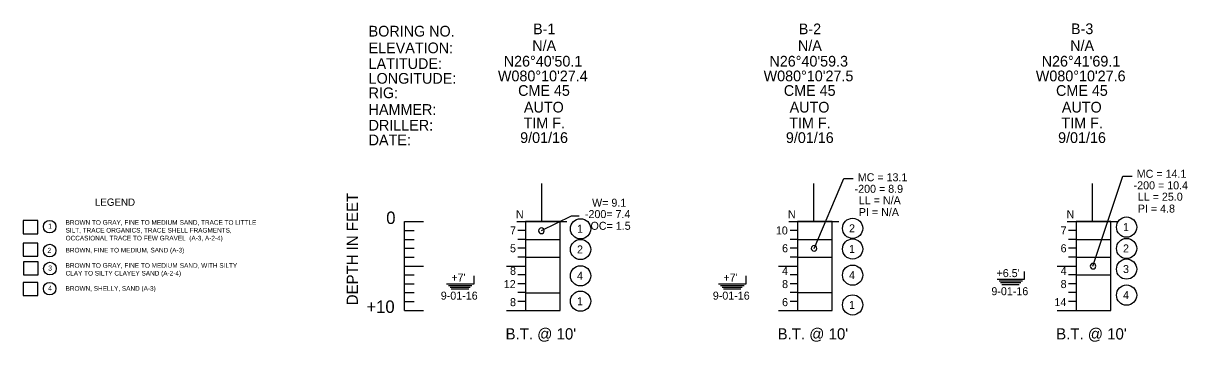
# Model space of a CAD drawing. Extents: x 0 to 331, y -72 to 117.
# Drawn here: x 9.92 to 45.01, y 22.82 to 32.42 of the extents above; entities that cross this region are included whole.
import ezdxf

# ---------------------------------------------------------------- set-up
doc = ezdxf.new("R2010")
doc.units = 0
for name, color, linetype in [('1-BORE', 7, 'Continuous'), ('1-GRID', 7, 'Continuous'), ('1-TEXT', 7, 'Continuous')]:
    doc.layers.add(name, color=color, linetype=linetype)

msp = doc.modelspace()

# ---------------------------------------------------------------- linework, layer by layer
at = {"layer": '1-BORE'}
for p, q in [((33.75, 25.629), (34.653, 27.737)), ((34.653, 27.737), (34.93, 27.738)), ((42.158, 25.092), (43.062, 27.802)), ((43.062, 27.802), (43.338, 27.803)), ((25.535, 26.168), (26.439, 26.607)), ((26.439, 26.607), (26.667, 26.607)), ((25.056, 25.902), (26.101, 25.902)), ((33.255, 25.902), (34.3, 25.902)), ((41.65, 25.902), (42.695, 25.902)), ((25.056, 25.366), (26.101, 25.366)), ((33.255, 25.366), (34.3, 25.366)), ((41.65, 25.366), (42.695, 25.366)), ((41.65, 24.83), (42.695, 24.83)), ((25.056, 24.294), (26.101, 24.294)), ((33.255, 24.295), (34.3, 24.295)), ((25.056, 23.759), (26.101, 23.759)), ((33.255, 23.759), (34.3, 23.759)), ((41.65, 23.759), (42.695, 23.759))]:
    msp.add_line(p, q, dxfattribs=at)
for points in [[(26.101, 23.759), (26.101, 26.438), (25.056, 26.438), (25.056, 23.759)], [(34.3, 23.759), (34.3, 26.438), (33.255, 26.438), (33.255, 23.759)], [(42.695, 23.759), (42.695, 26.438), (41.65, 26.438), (41.65, 23.759)]]:
    msp.add_lwpolyline(points, dxfattribs=at)
for centre, start, end in [((25.533, 26.161), 0, 180), ((25.533, 26.161), 180, 0), ((33.75, 25.631), 0, 180), ((33.75, 25.631), 180, 0), ((42.159, 25.094), 0, 180), ((42.159, 25.094), 180, 0)]:
    msp.add_arc(centre, 0.0848, start, end, dxfattribs=at)
at = {"layer": '1-GRID'}
for p, q in [((21.411, 26.438), (21.976, 26.438)), ((21.411, 26.17), (21.697, 26.17)), ((21.411, 25.902), (21.697, 25.902)), ((21.411, 25.634), (21.697, 25.634)), ((21.411, 25.366), (21.697, 25.366)), ((21.411, 25.098), (21.976, 25.098)), ((21.411, 25.098), (21.976, 25.098)), ((21.411, 24.83), (21.697, 24.83)), ((21.411, 24.563), (21.697, 24.563)), ((21.411, 24.295), (21.697, 24.295)), ((21.411, 24.027), (21.697, 24.027)), ((21.411, 23.759), (21.976, 23.759))]:
    msp.add_line(p, q, dxfattribs=at)
msp.add_lwpolyline([(21.411, 23.759), (21.411, 26.438)], dxfattribs=at)
at = {"layer": '1-TEXT'}
for p, q in [((25.535, 27.589), (25.535, 26.438)), ((33.735, 27.589), (33.735, 26.438)), ((42.13, 27.589), (42.13, 26.438)), ((25.056, 26.17), (24.826, 26.17)), ((33.255, 26.17), (33.026, 26.17)), ((41.65, 26.17), (41.421, 26.17)), ((25.056, 25.902), (24.826, 25.902)), ((25.056, 25.634), (24.826, 25.634)), ((33.255, 25.902), (33.026, 25.902)), ((33.255, 25.634), (33.026, 25.634)), ((41.65, 25.902), (41.421, 25.902)), ((41.65, 25.634), (41.421, 25.634)), ((25.056, 25.366), (24.826, 25.366)), ((33.255, 25.366), (33.026, 25.366)), ((41.65, 25.366), (41.421, 25.366)), ((24.482, 25.098), (25.056, 25.098)), ((32.682, 25.098), (33.255, 25.098)), ((40.097, 24.697), (40.097, 24.932)), ((41.077, 25.098), (41.65, 25.098)), ((23.502, 24.563), (23.502, 24.798)), ((25.056, 24.83), (24.826, 24.83)), ((31.702, 24.563), (31.702, 24.798)), ((33.255, 24.83), (33.026, 24.83)), ((39.272, 24.697), (40.097, 24.697)), ((39.326, 24.648), (40.036, 24.648)), ((39.374, 24.599), (39.98, 24.599)), ((41.65, 24.83), (41.421, 24.83)), ((22.677, 24.563), (23.502, 24.563)), ((22.731, 24.514), (23.441, 24.514)), ((22.779, 24.465), (23.385, 24.465)), ((22.817, 24.406), (23.342, 24.406)), ((25.056, 24.563), (24.826, 24.563)), ((25.056, 24.295), (24.826, 24.295)), ((30.876, 24.563), (31.702, 24.563)), ((30.931, 24.514), (31.641, 24.514)), ((30.978, 24.465), (31.585, 24.465)), ((31.017, 24.406), (31.541, 24.406)), ((33.255, 24.563), (33.026, 24.563)), ((33.255, 24.295), (33.026, 24.295)), ((39.412, 24.54), (39.937, 24.54)), ((41.65, 24.563), (41.421, 24.563)), ((41.65, 24.295), (41.421, 24.295)), ((25.056, 24.027), (24.826, 24.027)), ((33.255, 24.027), (33.026, 24.027)), ((41.65, 24.027), (41.421, 24.027)), ((24.482, 23.759), (25.056, 23.759)), ((32.682, 23.759), (33.255, 23.759)), ((41.077, 23.759), (41.65, 23.759))]:
    msp.add_line(p, q, dxfattribs=at)
for points in [[(9.918, 26.073), (10.36, 26.073), (10.36, 26.466), (9.918, 26.466)], [(9.918, 25.392), (10.36, 25.392), (10.36, 25.785), (9.918, 25.785)], [(9.924, 24.836), (10.366, 24.836), (10.366, 25.229), (9.924, 25.229)], [(9.918, 24.205), (10.36, 24.205), (10.36, 24.598), (9.918, 24.598)]]:
    msp.add_lwpolyline(points, close=True, dxfattribs=at)
for points in [[(24.789, 26.438), (26.298, 26.438)], [(32.989, 26.438), (34.498, 26.438)], [(41.384, 26.438), (42.893, 26.438)]]:
    msp.add_lwpolyline(points, dxfattribs=at)
for centre, radius in [((10.713, 26.285), 0.19), ((26.714, 26.22), 0.305), ((34.914, 26.234), 0.305), ((43.171, 26.271), 0.305), ((10.713, 25.562), 0.19), ((26.714, 25.596), 0.305), ((34.914, 25.611), 0.305), ((43.171, 25.626), 0.305), ((43.171, 25.006), 0.305), ((10.72, 25.02), 0.19), ((26.714, 24.803), 0.305), ((34.914, 24.823), 0.305), ((10.713, 24.416), 0.19), ((26.714, 24.037), 0.305), ((34.914, 23.925), 0.305), ((43.171, 24.221), 0.305)]:
    msp.add_circle(centre, radius, dxfattribs=at)

# ---------------------------------------------------------------- texts
at = {"layer": '1-GRID'}
msp.add_text('DEPTH IN FEET', height=0.3376, rotation=90, dxfattribs=at).set_placement((20.002, 23.916))
for s, height, p in [('0', 0.375, (20.857, 26.365)), ('+10', 0.3751, (20.259, 23.686))]:
    msp.add_text(s, height=height, dxfattribs=at).set_placement(p)
at = {"layer": '1-TEXT'}
for s, height, p in [('BORING NO.', 0.3231, (20.326, 32.016)), ('B-1', 0.3231, (25.283, 32.085)), ('B-2', 0.3231, (33.291, 32.085)), ('B-3', 0.3231, (41.495, 32.088)), ('ELEVATION:', 0.3231, (20.326, 31.513)), ('N/A', 0.3231, (25.258, 31.583)), ('N/A', 0.3231, (33.266, 31.583)), ('N/A', 0.3231, (41.47, 31.583)), ('LATITUDE:', 0.3231, (20.326, 31.038)), ("N26°40'50.1", 0.32313, (24.398, 31.111)), ("N26°40'59.3", 0.32313, (32.406, 31.111)), ("N26°41'69.1", 0.32313, (40.611, 31.111)), ('LONGITUDE:', 0.3231, (20.326, 30.594)), ("W080°10'27.4", 0.32313, (24.223, 30.667)), ("W080°10'27.5", 0.32313, (32.231, 30.667)), ("W080°10'27.6", 0.32313, (40.435, 30.667)), ('CME 45', 0.3231, (24.831, 30.228)), ('CME 45', 0.3231, (32.839, 30.228)), ('CME 45', 0.3231, (41.044, 30.228)), ('RIG:', 0.3231, (20.326, 30.158)), ('HAMMER:', 0.3231, (20.326, 29.655)), ('AUTO', 0.3231, (25.007, 29.726)), ('AUTO', 0.3231, (33.015, 29.725)), ('AUTO', 0.3231, (41.22, 29.725)), ('DRILLER:', 0.3231, (20.326, 29.181)), ('TIM F.', 0.3231, (24.995, 29.251)), ('TIM F.', 0.3231, (33.003, 29.251)), ('TIM F.', 0.3231, (41.207, 29.251)), ('9/01/16', 0.3231, (24.893, 28.807)), ('9/01/16', 0.3231, (32.902, 28.807)), ('9/01/16', 0.3231, (41.106, 28.807)), ('DATE:', 0.3231, (20.326, 28.737)), ('MC = 13.1', 0.2411, (35.068, 27.653)), ('MC = 14.1', 0.2411, (43.476, 27.758)), ('-200 = 8.9', 0.2411, (34.973, 27.305)), ('-200 = 10.4', 0.24114, (43.382, 27.41)), ('LEGEND', 0.22, (12.077, 26.913)), ('W= 9.1', 0.2411, (27.061, 26.886)), ('LL = N/A', 0.2411, (35.1, 26.962)), ('LL = 25.0', 0.2411, (43.509, 27.067)), ('N', 0.241, (24.765, 26.54)), ('-200= 7.4', 0.2411, (26.845, 26.543)), ('N', 0.241, (32.964, 26.54)), ('PI = N/A', 0.2411, (35.1, 26.604)), ('N', 0.241, (41.36, 26.54)), ('PI = 4.8', 0.2411, (43.509, 26.709)), ('1', 0.152, (10.667, 26.222)), ('BROWN TO GRAY, FINE TO MEDIUM', 0.14, (11.193, 26.342)), ('SAND, TRACE TO LITTLE ', 0.14, (14.631, 26.342)), ('1', 0.241, (26.607, 26.1)), ('OC= 1.5', 0.2411, (27.014, 26.19)), ('2', 0.241, (34.806, 26.114)), ('1', 0.241, (43.063, 26.151)), ('SILT, TRACE ORGANICS, TRACE SHELL FRAGMENTS, ', 0.14, (11.193, 26.106)), ('OCCASIONAL TRACE TO FEW GRAVEL  (A-3, A-2-4)', 0.14, (11.193, 25.87)), ('7', 0.241, (24.588, 26.049)), ('10', 0.2411, (32.6, 26.049)), ('7', 0.241, (41.182, 26.049)), ('2', 0.152, (10.645, 25.493)), ('BROWN, FINE TO MEDIUM, SAND (A-3)', 0.14, (11.193, 25.506)), ('5', 0.241, (24.588, 25.513)), ('2', 0.241, (26.607, 25.477)), ('6', 0.241, (32.787, 25.513)), ('1', 0.241, (34.806, 25.491)), ('6', 0.241, (41.182, 25.513)), ('2', 0.241, (43.063, 25.507)), ('3', 0.152, (10.667, 24.96)), ('CLAY TO SILTY CLAYEY SAND (A-2-4)', 0.14, (11.193, 24.81)), ('BROWN TO GRAY, FINE ', 0.14, (11.193, 25.045)), ('TO MEDIUM ', 0.14, (13.465, 25.045)), ('SAND, WITH SILTY ', 0.14, (14.635, 25.045)), ('8', 0.241, (24.588, 24.832)), ('4', 0.241, (26.607, 24.683)), ('4', 0.241, (32.787, 24.832)), ('4', 0.241, (34.806, 24.703)), ("+6.5'", 0.2411, (39.251, 24.764)), ('4', 0.241, (41.182, 24.832)), ('3', 0.241, (43.063, 24.886)), ("+7'", 0.2411, (22.819, 24.63)), ('12', 0.2411, (24.4, 24.433)), ("+7'", 0.2411, (31.019, 24.63)), ('8', 0.241, (32.787, 24.433)), ('8', 0.241, (41.182, 24.433)), ('4', 0.152, (10.667, 24.354)), ('BROWN, SHELLY, SAND (A-3) ', 0.14, (11.193, 24.353)), ('9-01-16', 0.2411, (22.501, 24.084)), ('9-01-16', 0.2411, (30.7, 24.084)), ('9-01-16', 0.2411, (39.096, 24.218)), ('4', 0.241, (43.063, 24.101)), ('8', 0.241, (24.588, 23.888)), ('1', 0.241, (26.607, 23.917)), ('6', 0.241, (32.787, 23.888)), ('1', 0.241, (34.806, 23.805)), ('14', 0.2411, (40.995, 23.888)), ("B.T. @ 10'", 0.3376, (24.454, 22.884)), ("B.T. @ 10'", 0.3376, (32.653, 22.884)), ("B.T. @ 10'", 0.3376, (41.049, 22.884))]:
    msp.add_text(s, height=height, dxfattribs=at).set_placement(p)

doc.saveas('drawing.dxf')
